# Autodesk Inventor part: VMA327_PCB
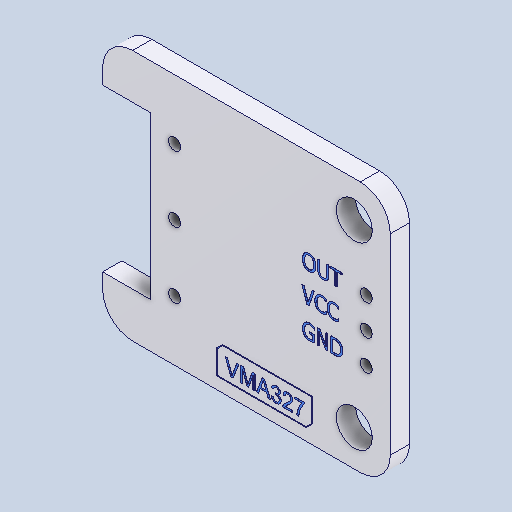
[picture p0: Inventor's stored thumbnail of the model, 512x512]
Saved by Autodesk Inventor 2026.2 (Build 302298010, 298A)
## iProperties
Created: 2023-02
Part Number: VMA327_PCB
Material: Generic
Document SubType Name: Modeling
Designer: mel
Density: 1 g/cm^3
Appearance: Par défaut
Author: mel
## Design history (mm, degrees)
feature "Solid1"
node "Solide1"
